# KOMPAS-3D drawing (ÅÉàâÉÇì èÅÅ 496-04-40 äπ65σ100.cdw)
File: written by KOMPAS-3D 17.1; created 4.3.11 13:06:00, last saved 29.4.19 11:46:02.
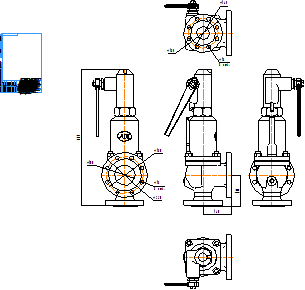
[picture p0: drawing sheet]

Sheet 1: A4, portrait

Title block, sheet 1: name: ПРЕГРАН КПП 496-04-40 Ду65х100; material: Сталь 10  ГОСТ 1050-88; mass: 41,48; sheets: 1; organisation: ООО "Торговый дом АДЛ"; sheet format: A4; stored path: C:\Users\tra\Desktop\2д чертежи\Предохранительные клапаны ПРЕГРАН\ПРЕГРАН 496\ПРЕГРАН КПП 496-04-40\KOMPAS 2D\Прегран Ду 65х100.cdw

Views: Спереди 4, Проекционный вид 5, Проекционный вид 6, Проекционный вид 7, Проекционный вид 8
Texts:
  Рама для чертежей
  Лит-Масса-Масштаб
  Материал-Предприятие
  Масштаб
  Изм.
  Лист
  № докум.
  Подп.
  Дата
  Лит.
  Разраб.
  Пров.
  Т.контр.
  Листов
  Внимание! Данный продукт является объектом авторского права ООО «Торговый Дом АДЛ».
  Запрещается изменение, копирование, распространение
  (в том числе путем копирования на другие сайты и ресурсы в Интернете)
  или любое иное использование информации и объектов без предварительного
  согласия правообладателя (ООО «Торговый Дом АДЛ»).
  Н.контр.
  Утв.
  Изменение
  Номер документа
  Подпись
  Обозначение документа
  Наименование изделия
  Масса изделия по ГОСТ 2.109-73
  Порядковый номер листа
  Общее количество листов в документе
  Характер работы, выполненной лицом, подписавшим документ
  Наименование или индекс предприятия, выпускающего документ
  Инв. № подл.
  Подп. и дата
  Взам. инв. №
  Инв. № дубл.
  Инвентарный номер подлинника по ГОСТ 2.501-68
  Подпись принявшего подлинник в отдел технической документации
  Инвентарный номер подлинника, взамен которого выпущен данный подлинник
  Инвентарный номер дубликата по ГОСТ 2.502-68
  Подпись принявшего дубликат в отдел технической документации
  Справ. №
  Перв. примен.
  Обозначение документа, взамен или на основании которого выпущен данный документ
  Обозначение документа, в котором впервые записан данный документ
  Подпись лица, копировавшего чертеж
  Обозначение формата листа
  !Рама для чертежа
Dimensions and other numbers on the sheet: 150; 140; 180; 18; 8 отв.; 100; 657; 220; 145; 185; 1:1; 1; 41,48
